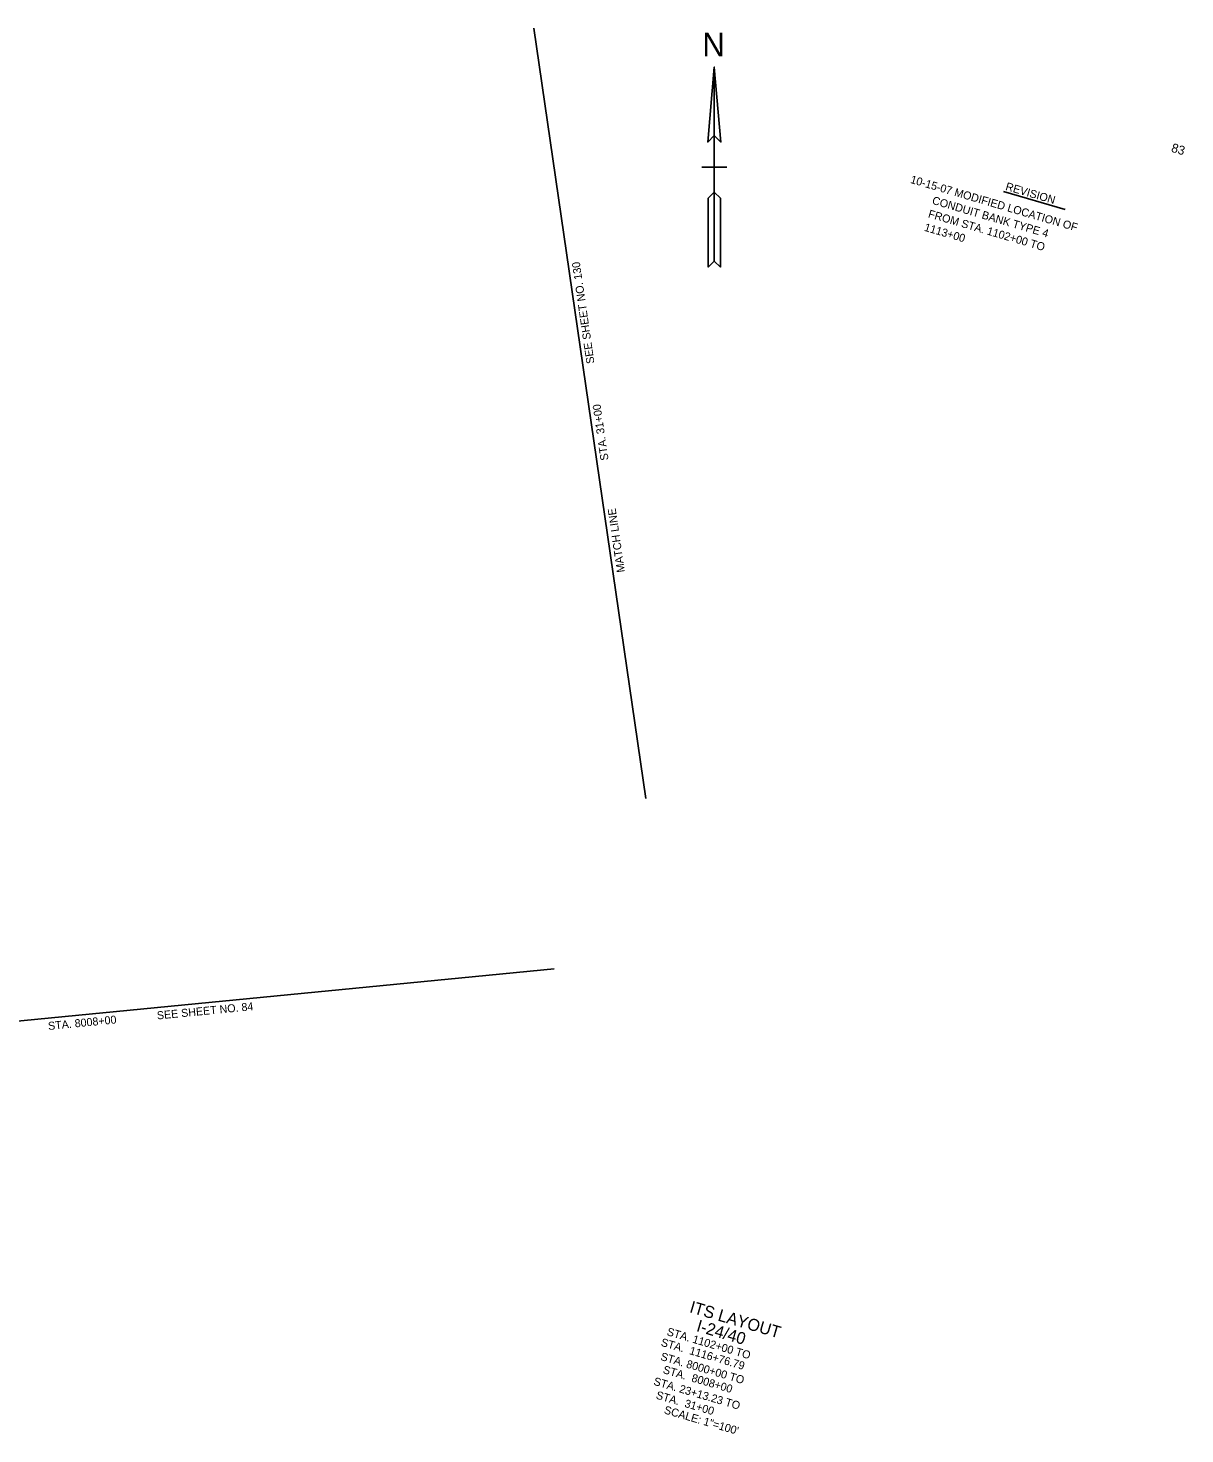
# Model space of a CAD drawing. Extents: x 1752043 to 1755533, y 656977 to 659403.
# Drawn here: x 1753797 to 1755533, y 656977 to 659085 of the extents above; entities that cross this region are included whole.
import ezdxf

# ---------------------------------------------------------------- set-up
doc = ezdxf.new("R2010")
doc.units = 0
for name, color, linetype in [('DESIGN - CENTERLINE - Proposed Text', 7, 'Continuous'), ('DESIGN - SCRATCH - User 1', 7, 'Continuous'), ('DESIGN - SHEET - Corner Text', 7, 'Continuous'), ('ITS - CONST TEXT', 7, 'Continuous'), ('ITS - EXISTING COMM CABLE', 7, 'Continuous'), ('ITS - EXISTING HAR', 7, 'Continuous')]:
    doc.layers.add(name, color=color, linetype=linetype)

msp = doc.modelspace()

# ---------------------------------------------------------------- linework, layer by layer
at = {"layer": 'DESIGN - CENTERLINE - Proposed Text'}
for p, q in [((1754827.1, 658877), (1754808.2, 658877)), ((1754846, 658877), (1754827.1, 658877))]:
    msp.add_line(p, q, dxfattribs=at)
msp.add_lwpolyline([(1754827.1, 659027), (1754817.3, 658914.4), (1754827.1, 658924.2), (1754836.9, 658914.4), (1754827.1, 659027), (1754827.1, 658736.1), (1754836.2, 658727), (1754836.2, 658830.5), (1754827.1, 658839.6), (1754818, 658830.5), (1754818, 658727), (1754827.1, 658736.1)], dxfattribs=at)
for points in [[(1754827.1, 658924.2), (1754836.9, 658914.4), (1754827.1, 659027)], [(1754818, 658727), (1754827.1, 658736.1), (1754827.1, 658839.6), (1754818, 658830.5)]]:
    msp.add_lwpolyline(points, close=True, dxfattribs=at)
at = {"layer": 'DESIGN - SCRATCH - User 1'}
msp.add_line((1754852, 657067.1), (1754852, 657067.1), dxfattribs=at)
msp.add_line((1754852, 657067.1), (1754852, 657067.1), dxfattribs=at)
at = {"layer": 'DESIGN - SHEET - Corner Text'}
msp.add_line((1755260.9, 658840.4), (1755353.8, 658813.2), dxfattribs=at)
at = {"layer": 'ITS - EXISTING COMM CABLE'}
for p, q in [((1754724.1, 657930.1), (1754556, 659085.4)), ((1753110.6, 657531.1), (1754586.5, 657674.5))]:
    msp.add_line(p, q, dxfattribs=at)

# ---------------------------------------------------------------- texts
at = {"layer": 'DESIGN - CENTERLINE - Proposed Text'}
msp.add_text('N', height=35.4, dxfattribs=at).set_placement((1754809, 659043.1))
at = {"layer": 'DESIGN - SHEET - Corner Text'}
for s, height, p in [('83', 13.5, (1755511.8, 658900.2)), ('10-15-07 MODIFIED LOCATION OF', 11.999, (1755120.4, 658853.4)), ('REVISION', 12, (1755263.2, 658842.9)), ('         CONDUIT BANK TYPE 4', 11.999, (1755114.5, 658833.2)), ('         FROM STA. 1102+00 TO', 11.999, (1755108.6, 658813.1)), ('         1113+00', 11.999, (1755102.7, 658792.9))]:
    msp.add_text(s, height=height, rotation=343.7088, dxfattribs=at).set_placement(p)
at = {"layer": 'ITS - CONST TEXT'}
msp.add_text('SCALE: 1"=100\'', height=12, rotation=343.7089, dxfattribs=at).set_placement((1754750.7, 657007.9))
at = {"layer": 'ITS - EXISTING COMM CABLE'}
for s, rotation, p in [('SEE SHEET NO. 130 ', 98.2795, (1754647.3, 658582.9)), ('STA. 31+00', 98.2795, (1754668.4, 658437.8)), ('MATCH LINE', 98.2795, (1754692.9, 658269.9)), ('SEE SHEET NO. 84 ', 5.5468, (1753991.1, 657598.5)), ('STA. 8008+00', 5.5468, (1753827.8, 657582.7))]:
    msp.add_text(s, height=12, rotation=rotation, dxfattribs=at).set_placement(p)
at = {"layer": 'ITS - EXISTING HAR'}
for s, height, p in [('ITS LAYOUT', 18, (1754788.8, 657159.6)), ('STA. 1102+00 TO', 12, (1754754.9, 657125.2)), ('I-24/40', 18, (1754799.1, 657131.4)), ('STA.  1116+76.79', 12, (1754746, 657109.3)), ('STA. 8000+00 TO', 12, (1754745.5, 657088)), ('STA.  8008+00', 12, (1754749.1, 657068.3)), ('STA. 23+13.23 TO', 12, (1754735, 657050.8)), ('STA.  31+00', 12, (1754738.7, 657030.1))]:
    msp.add_text(s, height=height, rotation=343.7089, dxfattribs=at).set_placement(p)

doc.saveas('drawing.dxf')
